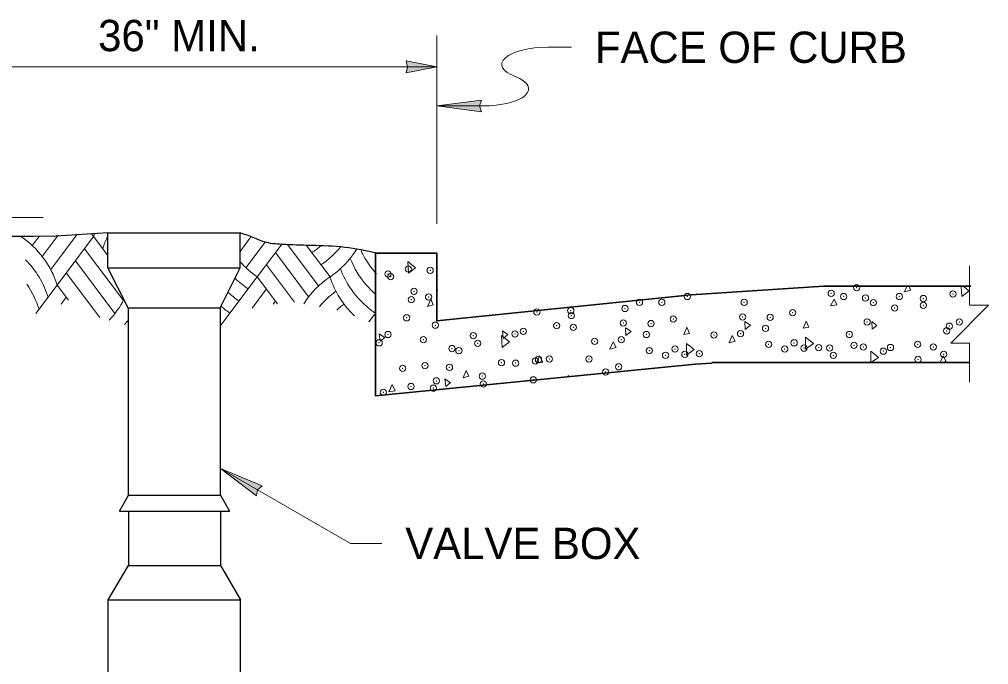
# Model space of a CAD drawing. Extents: x 99860 to 103153, y 99998 to 102077.
# Drawn here: x 101905.9 to 102400.9, y 100574 to 100903.5 of the extents above; entities that cross this region are included whole.
import ezdxf
from ezdxf.enums import TextEntityAlignment as Align

# ---------------------------------------------------------------- set-up
doc = ezdxf.new("R2010")
doc.units = 0
doc.header["$LTSCALE"] = 6.4
doc.header["$PDMODE"] = 32
doc.header["$PDSIZE"] = 3.2
for name, color, linetype, lineweight in [('10', 7, 'Continuous', 13), ('14', 7, 'Continuous', 13), ('15', 7, 'Continuous', 13), ('17', 7, 'Continuous', 35), ('18', 7, 'Continuous', 13), ('2', 7, 'Continuous', 13), ('20', 7, 'Continuous', 13), ('8', 7, 'Continuous', 25)]:
    doc.layers.add(name, color=color, linetype=linetype, lineweight=lineweight)

msp = doc.modelspace()

# ---------------------------------------------------------------- hatches: boundary and pattern name
at = {"layer": '14'}
msp.add_hatch(color=256, dxfattribs=at).paths.add_polyline_path([(102119.127, 100859.285), (102141.956, 100856.3), (102140.9, 100859.285), (102141.957, 100862.27)])
at = {"layer": '15'}
for points in [[(102119.127, 100879.285), (102103.402, 100876.201), (102104.13, 100879.285), (102103.402, 100882.369)], [(102008.664, 100674.145), (102026.942, 100660.146), (102027.518, 100663.26), (102029.927, 100665.316)]]:
    msp.add_hatch(color=256, dxfattribs=at).paths.add_polyline_path(points)

# ---------------------------------------------------------------- linework, layer by layer
at = {"layer": '10'}
for p, q in [((102104.539, 100773.947), (102104.264, 100779.835)), ((102108.239, 100776.622), (102104.264, 100779.835)), ((102104.539, 100773.947), (102108.239, 100776.622)), ((102119.427, 100764.935), (102119.127, 100767.56)), ((102119.427, 100767.31), (102119.127, 100767.56)), ((102358.014, 100764.347), (102359.064, 100767.072)), ((102361.189, 100765.185), (102360.139, 100767.072)), ((102387.214, 100761.985), (102386.964, 100767.072)), ((102390.977, 100764.935), (102388.052, 100767.072)), ((102114.377, 100756.922), (102115.952, 100760.685)), ((102117.302, 100757.722), (102115.952, 100760.685)), ((102320.202, 100757.197), (102322.089, 100760.685)), ((102323.377, 100757.722), (102322.089, 100760.685)), ((102358.014, 100764.347), (102361.189, 100765.185)), ((102387.214, 100761.985), (102390.977, 100764.935)), ((102114.377, 100756.922), (102117.302, 100757.722)), ((102320.202, 100757.197), (102323.377, 100757.722)), ((102215.702, 100742.022), (102215.452, 100746.035)), ((102218.352, 100744.16), (102215.452, 100746.035)), ((102245.239, 100742.585), (102246.789, 100746.285)), ((102248.139, 100743.072), (102246.789, 100746.285)), ((102276.577, 100745.172), (102276.327, 100749.185)), ((102306.114, 100745.76), (102307.689, 100749.422)), ((102306.114, 100745.76), (102309.039, 100746.247)), ((102309.039, 100746.247), (102307.689, 100749.422)), ((102341.477, 100745.235), (102341.239, 100749.21)), ((102090.164, 100739.135), (102089.639, 100742.835)), ((102092.539, 100740.985), (102089.639, 100742.835)), ((102090.164, 100739.135), (102092.539, 100740.985)), ((102152.389, 100735.922), (102152.114, 100742.022)), ((102156.127, 100738.822), (102152.114, 100742.022)), ((102152.914, 100740.46), (102152.677, 100744.435)), ((102155.327, 100742.585), (102152.677, 100744.435)), ((102152.914, 100740.46), (102155.327, 100742.585)), ((102215.702, 100742.022), (102218.352, 100744.16)), ((102245.239, 100742.585), (102248.139, 100743.072)), ((102268.339, 100738.297), (102269.939, 100741.997)), ((102271.514, 100739.097), (102269.939, 100741.997)), ((102307.439, 100735.122), (102307.439, 100741.222)), ((102311.452, 100738.022), (102307.439, 100741.222)), ((102152.389, 100735.922), (102156.127, 100738.822)), ((102207.439, 100735.147), (102209.077, 100738.822)), ((102207.439, 100735.147), (102210.639, 100735.922)), ((102210.639, 100735.922), (102209.077, 100738.822)), ((102246.539, 100731.947), (102246.539, 100738.047)), ((102250.552, 100734.872), (102246.539, 100738.047)), ((102268.339, 100738.297), (102271.514, 100739.097)), ((102307.439, 100735.122), (102311.452, 100738.022)), ((102169.939, 100727.935), (102171.539, 100731.672)), ((102173.152, 100728.485), (102171.539, 100731.672)), ((102246.539, 100731.947), (102250.552, 100734.872)), ((102340.714, 100728.21), (102340.714, 100734.072)), ((102344.664, 100730.897), (102340.714, 100734.072)), ((102340.714, 100728.21), (102344.664, 100730.897)), ((102376.077, 100728.21), (102377.652, 100731.672)), ((102379.289, 100728.772), (102377.652, 100731.672)), ((102169.939, 100727.935), (102173.152, 100728.485)), ((102376.602, 100728.21), (102379.289, 100728.772)), ((102132.477, 100720.51), (102134.052, 100724.235)), ((102132.477, 100720.51), (102135.377, 100721.31)), ((102135.377, 100721.31), (102134.052, 100724.235)), ((102186.164, 100720.747), (102186.164, 100721.547)), ((102186.964, 100721.022), (102186.164, 100721.547)), ((102094.664, 100713.285), (102096.302, 100717.047)), ((102097.852, 100713.872), (102096.302, 100717.047)), ((102123.689, 100715.997), (102123.127, 100719.985)), ((102126.089, 100717.847), (102123.127, 100719.985)), ((102123.689, 100715.997), (102126.089, 100718.135)), ((102094.664, 100713.285), (102097.852, 100713.872))]:
    msp.add_line(p, q, dxfattribs=at)
for points in [[(102276.577, 100745.172), (102279.252, 100747.297), (102276.327, 100749.185)], [(102341.477, 100745.235), (102343.889, 100747.085), (102341.239, 100749.21)]]:
    msp.add_lwpolyline(points, dxfattribs=at)
for p in [(102104.539, 100776.072), (102115.702, 100775.297), (102094.177, 100773.447), (102095.477, 100772.097), (102107.439, 100764.66), (102333.527, 100766.51), (102106.114, 100760.41), (102114.864, 100761.735), (102222.614, 100759.047), (102234.014, 100759.047), (102247.089, 100761.985), (102276.052, 100759.022), (102320.489, 100763.585), (102326.864, 100761.985), (102338.027, 100761.172), (102355.327, 100761.985), (102367.564, 100760.935), (102382.714, 100763.31), (102170.189, 100754.022), (102187.514, 100754.797), (102215.177, 100755.847), (102342.039, 100758.797), (102352.927, 100756.147), (102367.564, 100757.472), (102103.739, 100751.097), (102187.789, 100752.172), (102239.914, 100750.535), (102275.277, 100751.56), (102289.339, 100751.31), (102300.814, 100753.685), (102338.864, 100748.96), (102385.914, 100748.96), (102118.352, 100747.335), (102163.314, 100744.16), (102180.327, 100747.085), (102188.839, 100746.285), (102214.377, 100748.41), (102228.464, 100748.16), (102286.964, 100745.76), (102379.539, 100744.435), (102380.864, 100746.835), (102094.177, 100742.585), (102112.252, 100739.897), (102137.777, 100742.022), (102159.052, 100742.835), (102199.727, 100739.135), (102213.327, 100739.897), (102226.089, 100742.585), (102260.627, 100742.272), (102274.202, 100743.047), (102329.802, 100742.585), (102089.639, 100738.322), (102126.864, 100735.397), (102130.352, 100734.322), (102139.902, 100738.047), (102227.664, 100734.322), (102240.714, 100735.147), (102288.539, 100737.497), (102296.802, 100735.122), (102301.577, 100738.297), (102306.639, 100735.61), (102314.064, 100735.897), (102319.714, 100735.647), (102332.202, 100736.997), (102336.977, 100736.197), (102350.789, 100735.922), (102364.639, 100737.522), (102372.627, 100736.197), (102171.014, 100729.822), (102176.602, 100730.06), (102196.802, 100730.06), (102235.902, 100731.947), (102245.739, 100732.472), (102253.202, 100732.747), (102321.564, 100731.947), (102347.089, 100734.072), (102364.889, 100729.822), (102377.927, 100732.472), (102101.602, 100725.285), (102113.052, 100726.635), (102125.539, 100725.81), (102152.114, 100728.21), (102159.302, 100727.935), (102169.414, 100729.01), (102211.977, 100726.06), (102142.277, 100721.31), (102168.364, 100719.422), (102205.314, 100723.435), (102105.864, 100715.997), (102117.302, 100715.172), (102118.877, 100718.897), (102142.839, 100717.297), (102091.777, 100713.047)]:
    msp.add_point(p, dxfattribs=at)
at = {"layer": '14'}
for p, q in [((102175.862, 100889.285), (102187.862, 100889.285)), ((102119.127, 100859.285), (102142.558, 100859.285))]:
    msp.add_line(p, q, dxfattribs=at)
msp.add_lwpolyline([(102119.127, 100859.285), (102141.956, 100856.3), (102140.9, 100859.285), (102141.957, 100862.27)], close=True, dxfattribs=at)
for centre, start_param, end_param in [((102175.695, 100880.498), 4.7052439, 7.0686238), ((102142.558, 100868.072), 1.5707963, 3.926959)]:
    msp.add_ellipse(centre, major_axis=(-23.431, 0), ratio=0.375, start_param=start_param, end_param=end_param, dxfattribs=at)
at = {"layer": '15'}
for p, q in [((102119.127, 100799.085), (102119.127, 100895.285)), ((102119.127, 100879.285), (101855.602, 100879.285)), ((101883.539, 100802.41), (101918.039, 100802.41)), ((102008.664, 100674.145), (102074.978, 100635.859)), ((102074.978, 100635.859), (102090.978, 100635.859))]:
    msp.add_line(p, q, dxfattribs=at)
for points in [[(102119.127, 100879.285), (102103.402, 100876.201), (102104.13, 100879.285), (102103.402, 100882.369)], [(102008.664, 100674.145), (102026.942, 100660.146), (102027.518, 100663.26), (102029.927, 100665.316)]]:
    msp.add_lwpolyline(points, close=True, dxfattribs=at)
msp.add_lwpolyline([(102391.227, 100777.567), (102391.227, 100757.567), (102400.906, 100757.567), (102381.548, 100738.21), (102391.227, 100738.21), (102391.227, 100718.21)], dxfattribs=at)
at = {"layer": '17'}
for p, q in [((102248.939, 100762.785), (102316.752, 100767.31)), ((102391.777, 100767.31), (102316.752, 100767.31)), ((102391.227, 100728.21), (102259.552, 100728.21))]:
    msp.add_line(p, q, dxfattribs=at)
msp.add_lwpolyline([(102259.552, 100727.935), (102251.039, 100727.41), (102087.789, 100711.197), (102087.789, 100784.085), (102119.127, 100784.085), (102119.127, 100749.485), (102248.939, 100762.81), (102249.227, 100762.81)], dxfattribs=at)
at = {"layer": '18', "lineweight": 25}
for p, q in [((101951.064, 100776.597), (101951.064, 100794.422)), ((101951.064, 100794.422), (102018.602, 100794.422)), ((102018.602, 100776.597), (102018.602, 100794.422)), ((102008.477, 100756.122), (102018.602, 100776.597)), ((101961.389, 100756.122), (102008.477, 100756.122)), ((101961.577, 100660.56), (101961.577, 100756.122)), ((102008.664, 100660.56), (102008.664, 100756.122)), ((101957.077, 100652.297), (101961.577, 100660.56)), ((101961.577, 100660.56), (102008.664, 100660.56)), ((102008.664, 100660.56), (102013.202, 100652.297)), ((101957.077, 100652.297), (102013.202, 100652.297)), ((101961.577, 100652.297), (101961.577, 100624.635)), ((102008.664, 100652.297), (102008.664, 100624.635)), ((101951.214, 100607.085), (101961.577, 100624.635)), ((101961.577, 100624.635), (102008.664, 100624.635)), ((102008.664, 100624.635), (102018.777, 100607.085)), ((101951.214, 100551.772), (101951.214, 100607.085)), ((101951.214, 100607.085), (102018.777, 100607.085)), ((102018.777, 100551.772), (102018.777, 100607.085))]:
    msp.add_line(p, q, dxfattribs=at)
msp.add_lwpolyline([(101961.389, 100756.122), (101951.064, 100776.597), (102018.602, 100776.597)], dxfattribs=at)
at = {"layer": '2'}
for p, q in [((101912.475, 100787.98), (101915.938, 100792.597)), ((101915.938, 100792.597), (101916.233, 100792.991)), ((101917.572, 100782.401), (101925.219, 100792.597)), ((101921.876, 100775.765), (101934.5, 100792.597)), ((101925.219, 100792.597), (101925.809, 100793.384)), ((101925.219, 100767.848), (101943.781, 100792.597)), ((101934.5, 100792.597), (101935.385, 100793.778)), ((101942.671, 100794.077), (101943.781, 100792.597)), ((101943.781, 100792.597), (101951.064, 100782.886)), ((102018.602, 100784.999), (102024.17, 100792.423)), ((101939.14, 100786.41), (101958.999, 100759.931)), ((102021.598, 100776.62), (102031.396, 100789.684)), ((102027.416, 100772.003), (102040.02, 100788.808)), ((102042.725, 100788.714), (102058.721, 100767.385)), ((102052.424, 100788.156), (102064.539, 100772.003)), ((102036.697, 100784.377), (102053.625, 100761.807)), ((101934.5, 100780.223), (101954.695, 100753.296)), ((102032.056, 100778.19), (102046.355, 100759.125)), ((101929.859, 100774.036), (101946.934, 100751.27)), ((102008.855, 100747.255), (102027.416, 100772.003)), ((102027.416, 100772.003), (102037.732, 100758.248)), ((101914.326, 100753.325), (101925.219, 100767.848)), ((101925.219, 100767.848), (101930.968, 100760.184)), ((102024.729, 100756.045), (102032.056, 100765.816)), ((101927.168, 100758.072), (101929.859, 100761.661)), ((102035.491, 100758.02), (102036.697, 100759.628)), ((102084.427, 100749.024), (102087.918, 100753.678))]:
    msp.add_line(p, q, dxfattribs=at)
for centre, start, end in [((101880.457, 100753.612), 56.09536, 56.09634), ((101880.457, 100753.612), 17.6434, 56.09536), ((101988.543, 100778.36), 160.36493, 162.3566), ((101993.183, 100772.173), 154.22654, 162.3566), ((101993.183, 100772.173), 153.72579, 154.22661), ((102044.803, 100755.437), 123.90393, 123.90463), ((102029.058, 100823.363), 303.90361, 310.82747), ((102033.698, 100817.175), 303.90361, 320.60965), ((102038.338, 100810.988), 303.90361, 327.75149), ((102123.223, 100804.801), 204.25889, 211.33197), ((101875.816, 100747.425), 17.6434, 45.06433), ((102118.582, 100798.614), 201.43438, 220.94161), ((102123.221, 100804.801), 211.33188, 222.03912), ((102053.617, 100810.988), 221.8026, 236.09639), ((102113.942, 100792.427), 200.24322, 228.95992), ((102048.976, 100804.801), 225.47301, 236.09639), ((102090.74, 100733.017), 123.90361, 147.47509), ((102109.301, 100786.24), 197.6434, 226.73884), ((101871.176, 100741.237), 17.6434, 35.02567), ((102118.581, 100798.614), 220.94154, 229.56065), ((101917.58, 100782.085), 316.63377, 332.68399), ((102044.336, 100798.614), 227.35921, 236.09639), ((102095.38, 100726.83), 126.30626, 140.45867), ((102039.696, 100792.427), 229.22691, 236.09639), ((102100.021, 100720.643), 127.1006, 132.93339), ((102113.941, 100792.427), 228.95986, 236.09639), ((102104.661, 100714.456), 126.331, 126.528), ((101922.22, 100775.898), 322.75071, 326.73573), ((102035.056, 100786.24), 236.09549, 236.09602)]:
    msp.add_arc(centre, 46.972, start, end, dxfattribs=at)
at = {"layer": '8'}
msp.add_lwpolyline([(101951.064, 100794.422), (101924.727, 100792.847), (101913.039, 100792.597), (101900.277, 100792.597), (101886.714, 100792.597), (101871.814, 100792.847), (101855.602, 100793.372)], dxfattribs=at)
msp.add_spline([(102088.564, 100784.085), (102072.127, 100787.047), (102054.989, 100788.035), (102039.902, 100788.56), (102030.989, 100789.86), (102024.489, 100792.447), (102018.602, 100794.422)], degree=3, dxfattribs=at)

# ---------------------------------------------------------------- texts
at = {"layer": '20'}
msp.add_text('36" MIN.', height=16, dxfattribs=at).set_placement((101987.366, 100887.285), align=Align.CENTER)
for s, p in [('FACE OF CURB', (102199.862, 100881.285)), ('VALVE BOX', (102102.978, 100627.859))]:
    msp.add_text(s, height=16, dxfattribs=at).set_placement(p)

doc.saveas('drawing.dxf')
